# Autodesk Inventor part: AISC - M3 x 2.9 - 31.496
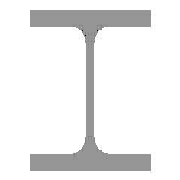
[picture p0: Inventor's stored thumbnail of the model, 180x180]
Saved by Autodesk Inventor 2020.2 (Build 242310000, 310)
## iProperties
Created: 2020-01
Part Number: AISC - M3 x 2.9 - 31.496
Material: Steel, Mild
Description: M-Shape
Document SubType Name: Modeling
Standard: ANSI
Designer: thira
Standards Organization: ANSI
Language: en-US
Size Designation: M3 x 2.9
Categories: <MemberInstance><Categories><Category DisplayName="Structural Shapes" InternalName="089c4875-fa83-4c05-b084-43b9cc11f5ed" Mnemonic="GRDR"><CategoryParameter Dis
Stock Number: M3 x 2.9
Density: 7.85 g/cm^3
Appearance: Semi-Polished
_CCFamilyMember: 14
_CCFamilyDisplayName: ANSI M - M-Shape — Sizes in parentheses have been withdrawn
_FrameMemberDoc: Frame Member File
_Version: 15.0.0
_GetPNFromCC: 1
G_L: 31.406 in
G_W: 2.250 in
G_H: 3.000 in
+F0858192-C1C7-41B0-A9F3-994A11C6D74B+CUTDETAIL1: Notch
+CE869F1B-091F-43B0-BEC0-5192978B821D+CUTDETAIL2: Notch
IsCustomPart: 1
Author: thira
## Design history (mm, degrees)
node "Start plane"
node "End plane"
sketch "Sketch"
  geometry: L1 (-28.575, -38.1)-(-28.575, -34.798); L2 (-28.575, -34.798)-(-10.541, -34.798); L3 (-1.143, -25.4)-(-1.143, 0); L4 (-1.143, 0)-(0, 0); L5 (0, 0)-(0, -38.1); L6 (0, -38.1)-(-28.575, -38.1); L7 (-60, 0)-(80, 0); L8 (0, -60)-(0, 80); L9 (28.575, -38.1)-(28.575, -34.798); L10 (28.575, -34.798)-(10.541, -34.798); L11 (0, -38.1)-(28.575, -38.1); L12 (1.143, -25.4)-(1.143, 0); L13 (1.143, 0)-(0, 0); L14 (-28.575, 38.1)-(-28.575, 34.798); L15 (0, 38.1)-(-28.575, 38.1); L16 (0, 38.1)-(28.575, 38.1); L17 (28.575, 34.798)-(10.541, 34.798); L18 (-28.575, 34.798)-(-10.541, 34.798); L19 (1.143, 25.4)-(1.143, 0); L20 (-1.143, 25.4)-(-1.143, 0); L21 (28.575, 38.1)-(28.575, 34.798); L22 (0, 108)-(0, -88) reference; L23 (-88, 0)-(108, 0) reference; A1 r 9.398 centre (-10.541, 25.4) between (-1.143, 25.4) and (-10.541, 34.798); A2 r 9.398 centre (10.541, 25.4) between (10.541, 34.798) and (1.143, 25.4); A3 r 9.398 centre (10.541, -25.4) between (1.143, -25.4) and (10.541, -34.798); A4 r 9.398 centre (-10.541, -25.4) between (-10.541, -34.798) and (-1.143, -25.4); 4 further points
  constraints: 42 end point, 11 symmetric about line, 8 point on circle, 8 point on line, 8 tangent, 4 centre point, 4 collinear, 4 parallel, 3 equal radius, 1 perpendicular, 1 vertical, 13 other
  dimensions: "d1" = 38.1 vertical distance of L1.start L3.end (= 0.5 x G_H); "d2" = 3.302 distance between parallel lines of L2 L6 (= G_T1); "d3" = 28.575 distance from line of L5.end L1 (= 0.5 x G_W); "d4" = 1.143 distance between parallel lines of L5 L3 (= 0.5 x G_T); "d13" = 9.398 radius of A1 (= G_IR)
extrude "Body" new body sketch "Sketch" stored distance "d5" = 797.714 (= G_L); taper "d6" = 0 deg
node "Driven Length"
  sketch "Sketch4"
    geometry: L1 (0, 0)-(10, 0) reference
    constraints: 2 end point, 1 horizontal
  workplane "Work Plane3"
  sketch "Sketch5"
    geometry: L1 (-2, 0)-(12, 0) reference; L2 (-2, 800)-(12, 800) reference
    dimensions: "d15" = 800 distance between parallel lines of L1 L2 (derived)
workplane "Work Plane4"
workplane "Work Plane5"
workplane "Work Plane6"
sketch "Sketch6"
  geometry: L1 (-28.575, -38.1)-(-28.575, -34.798); L2 (-28.575, -34.798)-(-10.541, -34.798); L3 (-1.143, -25.4)-(-1.143, 0); L4 (-1.143, 25.4)-(-1.143, 0); L5 (-28.575, 34.798)-(-10.541, 34.798); L6 (-28.575, 38.1)-(-28.575, 34.798); L7 (0, 38.1)-(-28.575, 38.1); L8 (0, 38.1)-(28.575, 38.1); L9 (28.575, 38.1)-(28.575, 34.798); L10 (28.575, 34.798)-(10.541, 34.798); L11 (1.143, 25.4)-(1.143, 0); L12 (1.143, -25.4)-(1.143, 0); L13 (28.575, -34.798)-(10.541, -34.798); L14 (28.575, -38.1)-(28.575, -34.798); L15 (0, -38.1)-(28.575, -38.1); L16 (0, -38.1)-(-28.575, -38.1); A1 r 9.398 centre (-10.541, -25.4) between (-10.541, -34.798) and (-1.143, -25.4); A2 r 9.398 centre (-10.541, 25.4) between (-1.143, 25.4) and (-10.541, 34.798); A3 r 9.398 centre (10.541, 25.4) between (10.541, 34.798) and (1.143, 25.4); A4 r 9.398 centre (10.541, -25.4) between (1.143, -25.4) and (10.541, -34.798)
  constraints: 32 end point, 8 point on circle, 4 centre point
extrude "Extrusion2" new body sketch "Sketch6" stored distance "d16" = 3.302; taper "d17" = 0 deg
combine "Combine1"
  body "Solid2"
workplane "Work Plane7"
workplane "Work Plane8"
workplane "Work Plane9"
sketch "Sketch7"
  geometry: L1 (-28.575, -38.1)-(-28.575, -34.798); L2 (-28.575, -34.798)-(-10.541, -34.798); L3 (-1.143, -25.4)-(-1.143, 0); L4 (-1.143, 25.4)-(-1.143, 0); L5 (-28.575, 34.798)-(-10.541, 34.798); L6 (-28.575, 38.1)-(-28.575, 34.798); L7 (0, 38.1)-(-28.575, 38.1); L8 (0, 38.1)-(28.575, 38.1); L9 (28.575, 38.1)-(28.575, 34.798); L10 (28.575, 34.798)-(10.541, 34.798); L11 (1.143, 25.4)-(1.143, 0); L12 (1.143, -25.4)-(1.143, 0); L13 (28.575, -34.798)-(10.541, -34.798); L14 (28.575, -38.1)-(28.575, -34.798); L15 (0, -38.1)-(28.575, -38.1); L16 (0, -38.1)-(-28.575, -38.1); A1 r 9.398 centre (-10.541, -25.4) between (-10.541, -34.798) and (-1.143, -25.4); A2 r 9.398 centre (-10.541, 25.4) between (-1.143, 25.4) and (-10.541, 34.798); A3 r 9.398 centre (10.541, 25.4) between (10.541, 34.798) and (1.143, 25.4); A4 r 9.398 centre (10.541, -25.4) between (1.143, -25.4) and (10.541, -34.798)
  constraints: 32 end point, 8 point on circle, 4 centre point
extrude "Extrusion3" new body sketch "Sketch7" stored distance "d18" = 3.302; taper "d19" = 0 deg
combine "Combine2"
  body "Solid3"
body "Solid1"
other parameters: "G_W" = 57.15 [user parameter; used in 1 equation term], "G_H" = 76.2 [user parameter; used in 1 equation term], "G_T" = 2.286 [user parameter; used in 1 equation term], "G_T1" = 3.302 [user parameter; used in 1 equation term], "G_IR" = 9.398 [user parameter; used in 1 equation term], "G_L" = 797.714 [user parameter; used in 1 equation term], "G_OFFSET_START" = 0 [user parameter; used in 1 equation term], "G_OFFSET_END" = 0 [user parameter; used in 1 equation term], "d11" = 0 (computed from G_OFFSET_START), "d12" = 800 (= G_OFFSET_END + B_L), "B_L" = 800 [user parameter; used in 1 equation term], "d14" = 90 deg
